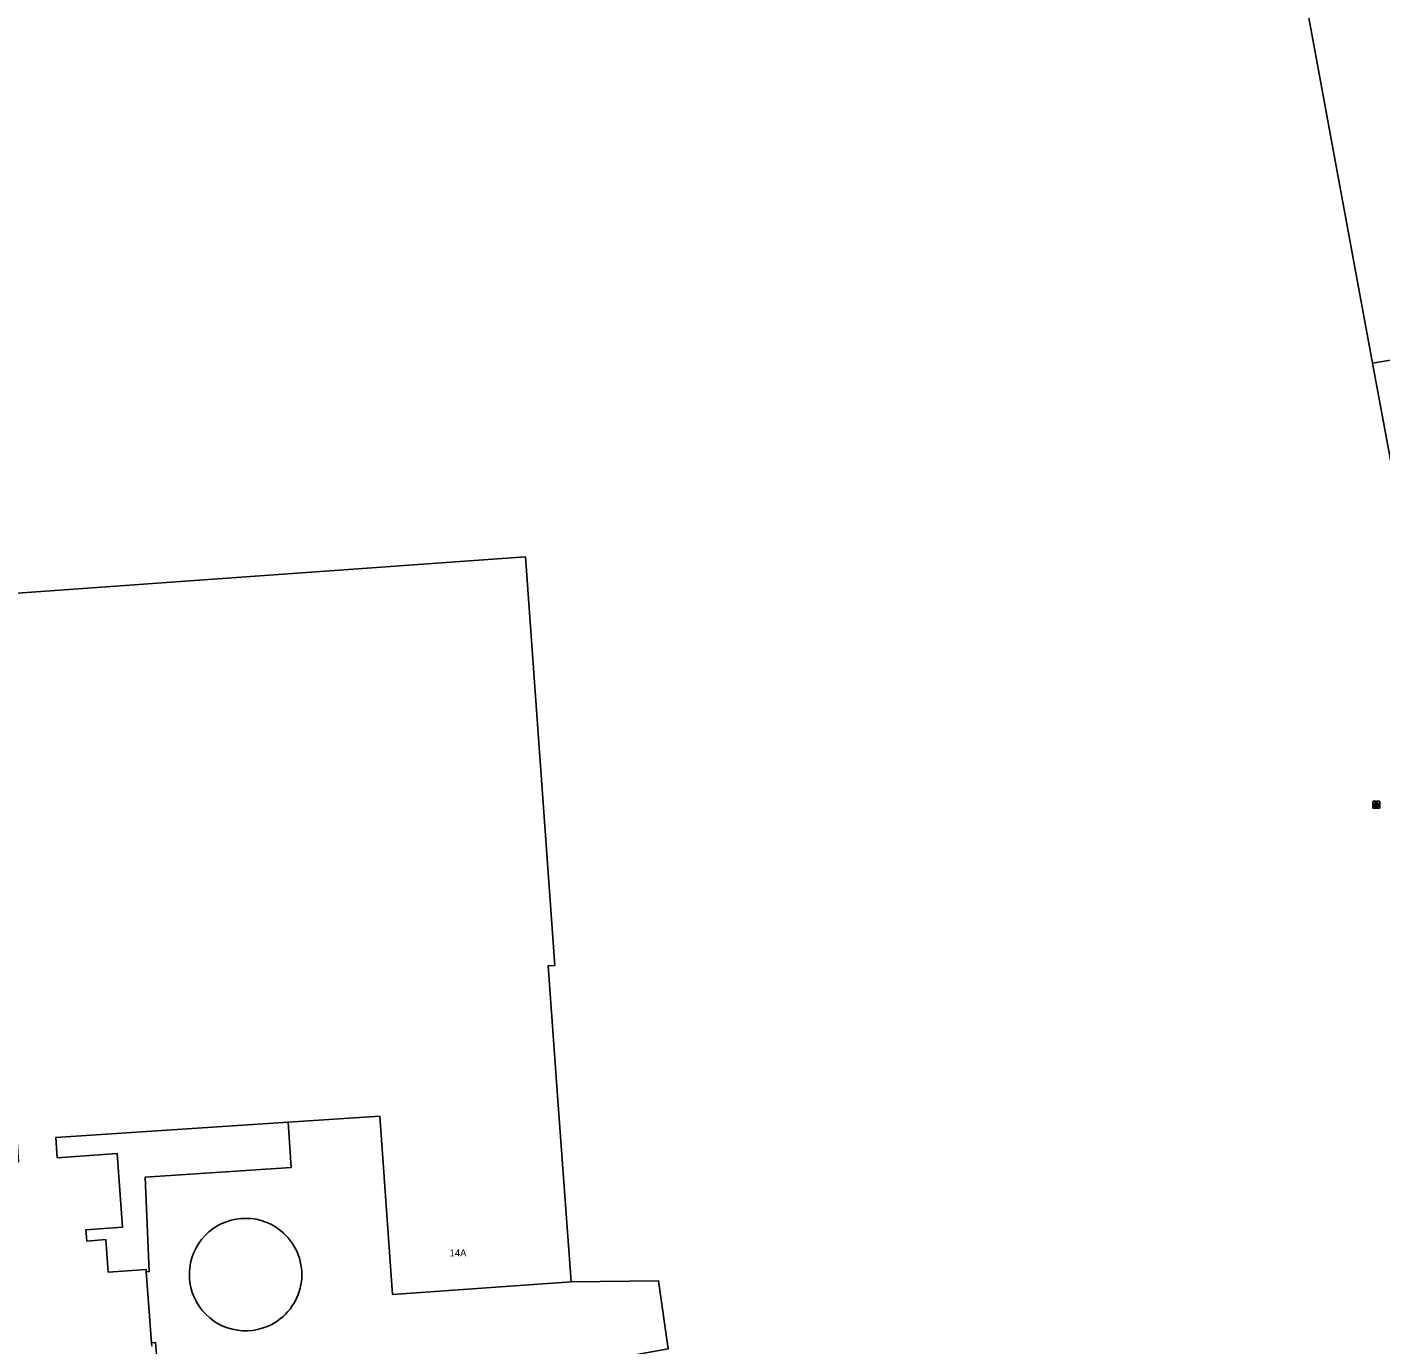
# Model space of a CAD drawing. Extents: x 162510 to 163918, y 388494 to 389774.
# Drawn here: x 162828.3 to 163019.4, y 389100.2 to 389286.2 of the extents above; entities that cross this region are included whole.
import ezdxf

# ---------------------------------------------------------------- set-up
doc = ezdxf.new("R2010")
doc.units = 0
for name, color, linetype in [('IMGEO_Boomteelt', 7, 'Continuous'), ('IMGEO_Erf', 7, 'Continuous'), ('IMGEO_Groenvoorziening', 7, 'Continuous'), ('IMGEO_Pand', 7, 'Continuous'), ('IMGEO_Pand_nummerreeks', 7, 'Continuous'), ('IMGEO_Rijbaan_lokaal_gesloten', 7, 'Continuous'), ('IMGEO_Rioolput', 7, 'Continuous')]:
    doc.layers.add(name, color=color, linetype=linetype)

msp = doc.modelspace()

# ---------------------------------------------------------------- linework, layer by layer
at = {"layer": 'IMGEO_Boomteelt'}
for points in [[(163060.88, 389326.63), (163073.46, 389248.06), (163018.26, 389238.8), (163036.74, 389139.46), (163090.38, 389144.83), (163103.59, 389146.15), (163108.55, 389146.78), (163110.9, 389147.04), (163144.72, 389150.93), (163149.82, 389151.52), (163170.3, 389153.88), (163195.3, 389156.75), (163160.97, 389342.79), (163140.33, 389340.02), (163113.83, 389336.05)], [(163060.88, 389326.63), (163005.58, 389316.78), (163004.84, 389316.63), (163003.95, 389316.44), (163018.26, 389238.8), (163073.46, 389248.06)]]:
    msp.add_lwpolyline(points, close=True, dxfattribs=at)
at = {"layer": 'IMGEO_Erf'}
for points in [[(163036.74, 389139.46), (163018.26, 389238.8), (163003.95, 389316.44)], [(162826.65, 389089.65), (162824.12, 389125.82), (162827.03, 389126.03), (162826.83, 389128.86), (162796.15, 389126.87), (162790.64, 389203.73), (162898.66, 389211.45), (162902.77, 389153.76), (162901.82, 389153.69), (162903.23, 389134.09), (162905.07, 389109.1), (162917.44, 389109.24), (162918.81, 389099.65)], [(162846.81, 389095.43), (162846.39, 389100.52), (162845.82, 389100.5), (162845.85, 389100.03)]]:
    msp.add_lwpolyline(points, dxfattribs=at)
msp.add_lwpolyline([(162865.12, 389131.64), (162832.3, 389129.47), (162832.51, 389126.59), (162840.98, 389127.21), (162841.74, 389116.83), (162836.56, 389116.45), (162836.68, 389114.86), (162839.36, 389115.06), (162839.7, 389110.46), (162845.07, 389110.85), (162845.09, 389110.53), (162845.51, 389110.55), (162844.91, 389123.87), (162865.54, 389125.25)], close=True, dxfattribs=at)
at = {"layer": 'IMGEO_Groenvoorziening'}
for start, end in [(57.9872, 308.4313), (308.4344, 57.984)]:
    msp.add_arc((162859.11, 389110.12), 7.94, start, end, dxfattribs=at)
at = {"layer": 'IMGEO_Pand'}
msp.add_lwpolyline([(162845.85, 389100.03), (162845.82, 389100.5), (162845.09, 389110.53), (162845.07, 389110.85), (162839.7, 389110.46), (162839.36, 389115.06), (162836.68, 389114.86), (162836.56, 389116.45), (162841.74, 389116.83), (162840.98, 389127.21), (162832.51, 389126.59), (162832.3, 389129.47), (162865.12, 389131.64), (162878.06, 389132.5), (162879.88, 389107.29), (162905.07, 389109.1), (162903.23, 389134.09), (162901.82, 389153.69), (162902.77, 389153.76), (162898.66, 389211.45), (162790.64, 389203.73)], dxfattribs=at)
at = {"layer": 'IMGEO_Rijbaan_lokaal_gesloten'}
msp.add_lwpolyline([(162906.83, 389097.48), (162918.81, 389099.65), (162917.44, 389109.24), (162905.07, 389109.1), (162879.88, 389107.29), (162878.06, 389132.5), (162865.12, 389131.64), (162865.54, 389125.25), (162844.91, 389123.87), (162845.51, 389110.55), (162845.09, 389110.53), (162845.82, 389100.5), (162846.39, 389100.52), (162846.81, 389095.43), (162868.4, 389097), (162868.38, 389097.39)], dxfattribs=at)
for start, end in [(57.9872, 308.4313), (308.4344, 57.984)]:
    msp.add_arc((162859.11, 389110.12), 7.94, start, end, dxfattribs=at)
at = {"layer": 'IMGEO_Rioolput'}
for p, q in [((163018.3, 389176.03), (163018.3, 389176.88)), ((163018.37, 389176.96), (163019.22, 389176.96)), ((163018.78, 389176.74), (163018.81, 389176.74)), ((163019.3, 389176.88), (163019.3, 389176.03)), ((163019.22, 389175.96), (163018.37, 389175.96)), ((163018.55, 389176.45), (163018.55, 389176.46)), ((163018.99, 389176.41), (163018.59, 389176.41)), ((163018.6, 389176.5), (163019, 389176.5)), ((163018.81, 389176.18), (163018.78, 389176.18)), ((163019.04, 389176.46), (163019.04, 389176.45))]:
    msp.add_line(p, q, dxfattribs=at)
for points in [[(163018.3, 389176.03), (163018.3, 389176.88)], [(163018.37, 389176.96), (163019.22, 389176.96)], [(163019.3, 389176.88), (163019.3, 389176.03)], [(163019.22, 389175.96), (163018.37, 389175.96)]]:
    msp.add_lwpolyline(points, dxfattribs=at)
for centre, radius, start, end in [((163018.37, 389176.88), 0.0765, 91.552, 178.448), ((163018.37, 389176.88), 0.0765, 91.552, 178.448), ((163019.22, 389176.88), 0.0765, 1.552, 88.448), ((163019.22, 389176.88), 0.0765, 1.552, 88.448), ((163018.37, 389176.03), 0.0765, 181.552, 268.448), ((163018.37, 389176.03), 0.0765, 181.552, 268.448), ((163018.6, 389176.46), 0.0403, 85.8775, 175.7526), ((163018.59, 389176.45), 0.0366, 178.938, 274.7102), ((163019, 389176.46), 0.043, 264.8664, 352.4533), ((163019, 389176.46), 0.0386, 1.7309, 96.639), ((163019.22, 389176.03), 0.0765, 271.552, 358.448), ((163019.22, 389176.03), 0.0765, 271.552, 358.448)]:
    msp.add_arc(centre, radius, start, end, dxfattribs=at)
for centre, major_axis, ratio, start_param, end_param in [((163018.78, 389176.46), (-0.387, 0.002), 0.722429, 4.712389, 7.853982), ((163018.81, 389176.46), (-0.39, 0.002), 0.717154, 1.570796, 4.712389)]:
    msp.add_ellipse(centre, major_axis=major_axis, ratio=ratio, start_param=start_param, end_param=end_param, dxfattribs=at)

# ---------------------------------------------------------------- texts
at = {"layer": 'IMGEO_Pand_nummerreeks'}
msp.add_text('14A', height=1, dxfattribs=at).set_placement((162887.92, 389112.68))

doc.saveas('drawing.dxf')
